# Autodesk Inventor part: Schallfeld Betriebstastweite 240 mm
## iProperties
Shininess: 20.0
Length Units: 11269
Angle Units: 11279
Time Units: 11290
Mass Units: 11283
Length Display Precision: 2
Angle Display Precision: 2
Part Number: Schallfeld Betriebstastweite 240 mm
Material: Lexan (klar)
Document SubType Name: Modellieren
Checked By: Alves
Created: 2005-08
Designer: Grube
Manufacturer: Standard
Standards Organization: Custom
Description: Schallfeld 0,24m
Density: 0.0
Volumn: 0.0
Area: 0.0
PropertySet Name: Model Information
Control State: 0
Master: False
Checked Out: False
Last Check In By: Kramp
Last Check In Date: 2005-08-11
ME: ST
Comments: keine Bemerkung
Title: Schallfelder
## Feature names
1. Platte [Revolution]
